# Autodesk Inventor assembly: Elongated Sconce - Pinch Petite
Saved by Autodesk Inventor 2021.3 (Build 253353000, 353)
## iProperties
Created: 2022-08
Part Number: Elongated Sconce - Pinch Petite
Document SubType Name: Assembly
Designer: Administrator
Title: Elongated Sconce - Pinch Petite v7
Author: Administrator
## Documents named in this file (11)
- c:\worker\convert-fusion-r04\tmp\job-1\56\output\files\d3cb649a-3824-4a81-bcfd-3f16e6c30d87\48ec22c4-2c4f-4552-a58c-49bb488fe2db.iam
- c:\worker\convert-fusion-r04\tmp\job-1\56\output\files\d3cb649a-3824-4a81-bcfd-3f16e6c30d87\Back Plate.ipt
- c:\worker\convert-fusion-r04\tmp\job-1\56\output\files\d3cb649a-3824-4a81-bcfd-3f16e6c30d87\Knurled Shade Ring.ipt
- c:\worker\convert-fusion-r04\tmp\job-1\56\output\files\d3cb649a-3824-4a81-bcfd-3f16e6c30d87\Screw Top.ipt
- c:\worker\convert-fusion-r04\tmp\job-1\56\output\files\d3cb649a-3824-4a81-bcfd-3f16e6c30d87\Sconce.ipt
- c:\worker\convert-fusion-r04\tmp\job-1\56\output\files\d3cb649a-3824-4a81-bcfd-3f16e6c30d87\Socket Cover.ipt
- c:\worker\convert-fusion-r04\tmp\job-1\56\output\files\d3cb649a-3824-4a81-bcfd-3f16e6c30d87\Screw Bottom.ipt
- c:\worker\convert-fusion-r04\tmp\job-1\56\output\files\d3cb649a-3824-4a81-bcfd-3f16e6c30d87\Socket - E26.ipt
- c:\worker\convert-fusion-r04\tmp\job-1\56\output\files\d3cb649a-3824-4a81-bcfd-3f16e6c30d87\T9-Bulb.ipt
- c:\worker\convert-fusion-r04\tmp\job-1\56\output\files\d3cb649a-3824-4a81-bcfd-3f16e6c30d87\E26 Base.ipt
- c:\worker\convert-fusion-r04\tmp\job-1\56\output\files\d3cb649a-3824-4a81-bcfd-3f16e6c30d87\Part20.ipt
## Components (10 placed, 10 different names)
1. Back Plate:1
2. Knurled Shade Ring:1
3. Screw Top:1
4. Sconce:1
5. Socket Cover:1
6. Screw Bottom:1
7. Socket - E26:1
8. T9-Bulb:1
9. E26 Base:1
10. Part20
